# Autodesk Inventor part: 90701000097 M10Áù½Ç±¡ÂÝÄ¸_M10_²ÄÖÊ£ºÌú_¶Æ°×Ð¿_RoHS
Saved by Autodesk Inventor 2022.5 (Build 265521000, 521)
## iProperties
Created: 2025-02
Part Number: 90701000097 M10Áù½Ç±¡ÂÝÄ¸_M10_²ÄÖÊ£ºÌú_¶Æ°×Ð¿_RoHS
Material: Generic
Document SubType Name: Modeling
Designer: AdminForWorker
Density: 1 g/cm^3
Appearance: Default
Title: 90701000097 M10Áù½Ç±¡ÂÝÄ¸_M10_²ÄÖÊ£ºÌú_¶Æ°×Ð¿_RoHS
Author: AdminForWorker
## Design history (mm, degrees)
feature "Body1"
feature "Composite1"
body "Solid1"
body "Srf1"
